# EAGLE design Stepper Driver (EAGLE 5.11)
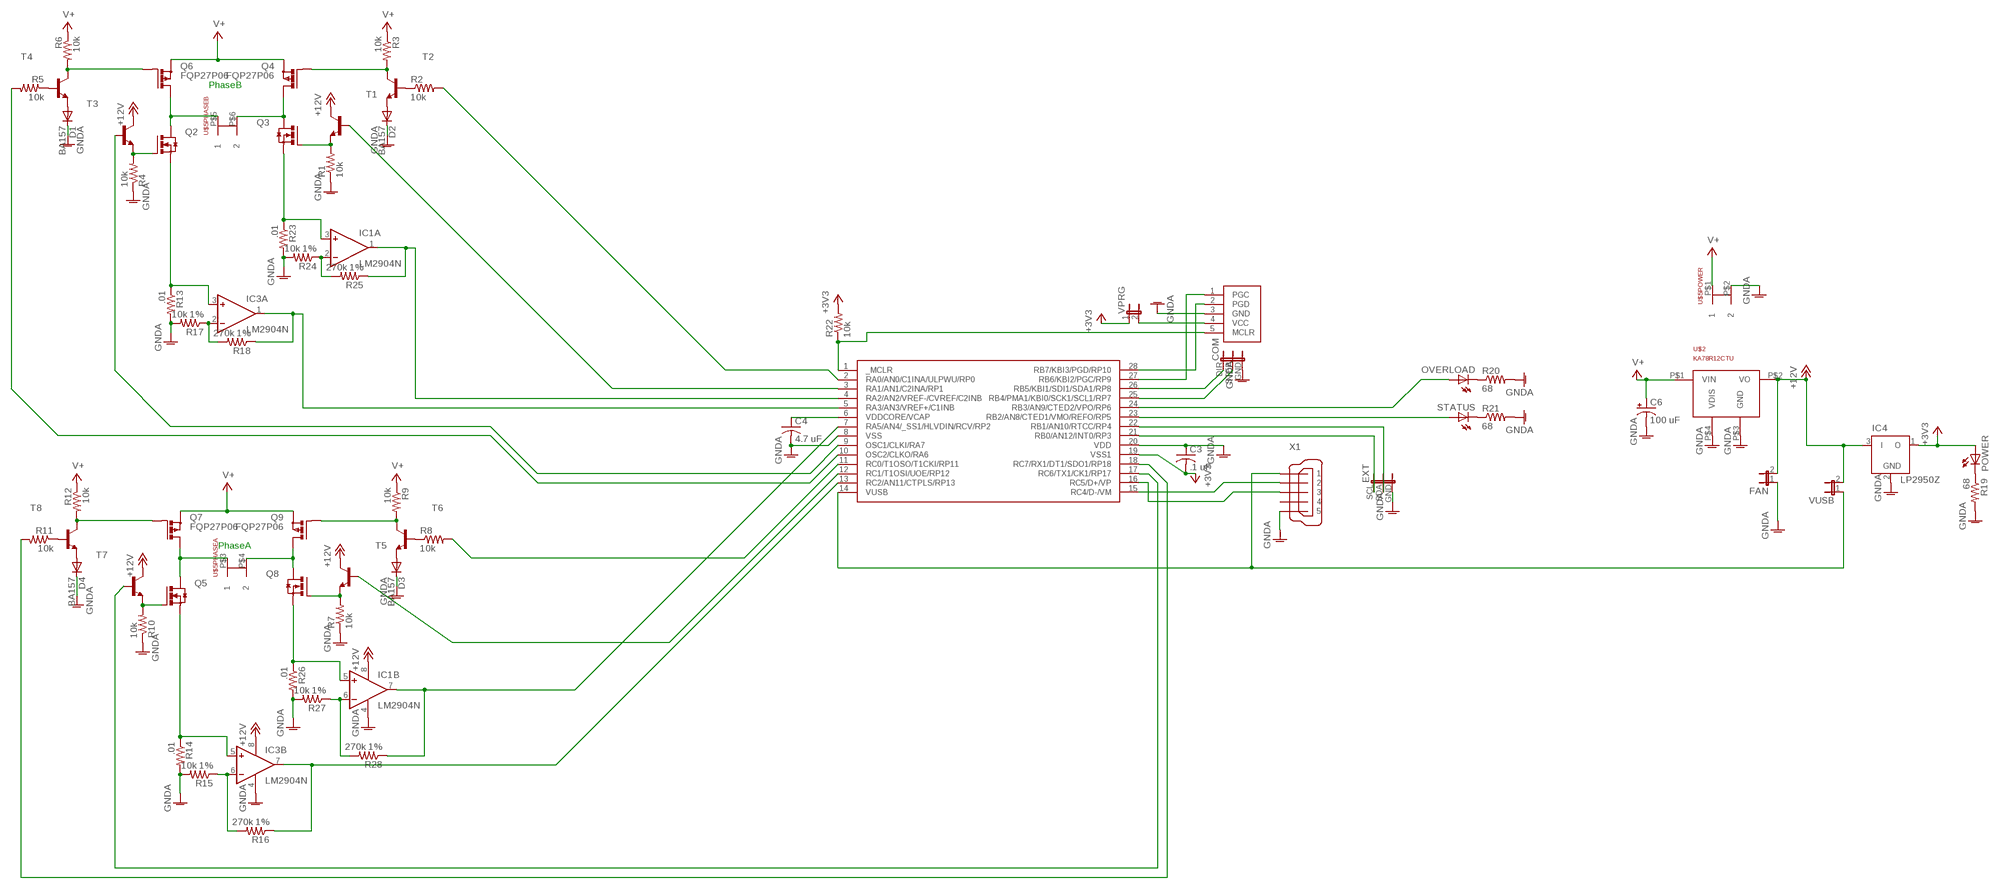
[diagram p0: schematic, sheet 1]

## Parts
C3  .1 uF  C-US025-024X044  [C025-024X044]
C4  4.7 uF  C-US025-024X044  [C025-024X044]
C6  100 uF  CPOL-USE5-10.5  [E5-10,5]
COM  COM  [COM]
D1  BA157  [P1-10]
D2  BA157  [P1-10]
D3  BA157  [P1-10]
D4  BA157  [P1-10]
EXT  I2C  [I2C]
FAN  JP1E  [JP1]
IC1  LM2904N  LM358N  [DIL08]
IC3  LM2904N  LM358N  [DIL08]
IC4  LP2950Z  [TO92]
OVERLOAD  LED3MM  [LED3MM]
POWER  LED3MM  [LED3MM]
Q2  IRF3704L-V  [TO262-V]
Q3  IRF3704L-V  [TO262-V]
Q4  FQP27P06  PMOSFET_PTO220BV  [TO220BV]
Q5  IRF3704L-V  [TO262-V]
Q6  FQP27P06  PMOSFET_PTO220BV  [TO220BV]
Q7  FQP27P06  PMOSFET_PTO220BV  [TO220BV]
Q8  IRF3704L-V  [TO262-V]
Q9  FQP27P06  PMOSFET_PTO220BV  [TO220BV]
R1  10k  R-US_0207/7  [0207/7]
R2  10k  R-US_0207/7  [0207/7]
R3  10k  R-US_0207/7  [0207/7]
R4  10k  R-US_0207/7  [0207/7]
R5  10k  R-US_0207/7  [0207/7]
R6  10k  R-US_0207/7  [0207/7]
R7  10k  R-US_0207/7  [0207/7]
R8  10k  R-US_0207/7  [0207/7]
R9  10k  R-US_0207/7  [0207/7]
R10  10k  R-US_0207/7  [0207/7]
R11  10k  R-US_0207/7  [0207/7]
R12  10k  R-US_0207/7  [0207/7]
R13  .01  R-US_0207/7  [0207/7]
R14  .01  R-US_0207/7  [0207/7]
R15  10k 1%  R-US_0207/7  [0207/7]
R16  270k 1%  R-US_0207/7  [0207/7]
R17  10k 1%  R-US_0207/7  [0207/7]
R18  270k 1%  R-US_0207/7  [0207/7]
R19  68  R-US_0207/7  [0207/7]
R20  68  R-US_0207/7  [0207/7]
R21  68  R-US_0207/7  [0207/7]
R22  10k  R-US_0207/7  [0207/7]
R23  .01  R-US_0207/7  [0207/7]
R24  10k 1%  R-US_0207/7  [0207/7]
R25  270k 1%  R-US_0207/7  [0207/7]
R26  .01  R-US_0207/7  [0207/7]
R27  10k 1%  R-US_0207/7  [0207/7]
R28  270k 1%  R-US_0207/7  [0207/7]
STATUS  LED3MM  [LED3MM]
T1  -NPN-TO92-EBC  [TO92-EBC]
T2  -NPN-TO92-EBC  [TO92-EBC]
T3  -NPN-TO92-EBC  [TO92-EBC]
T4  -NPN-TO92-EBC  [TO92-EBC]
T5  -NPN-TO92-EBC  [TO92-EBC]
T6  -NPN-TO92-EBC  [TO92-EBC]
T7  -NPN-TO92-EBC  [TO92-EBC]
T8  -NPN-TO92-EBC  [TO92-EBC]
U$1  ICSP_HEADER  [ICSP_HEADER]
U$2  KA78R12CTU  [TO220-4]
U$3  PIC18F24J50  [DIL28-3]
U$5  6P_TERMINAL_BLOCK_5.08MM  [6P_TERMINAL_BLOCK_5_08MM]
VPRG  JP1E  [JP1]
VUSB  JP1E  [JP1]
X1  MINI-USB-32005-301  [32005-301]

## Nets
21: EXT.SCL U$3.21(RB0/AN12/INT0/RP3)
+3V3: C3.2 IC4.1(O) POWER.A R22.2 U$3.19(VSS1) VPRG.1
+12V: FAN.2 IC1.8(P:V+) IC3.8(P:V+) IC4.3(I) T1.C T3.C T5.C T7.C U$2.P$2(VO) VUSB.2
GNDA: C3.1 C4.2 C6.- COM.GND D1.C D2.C D3.C D4.C EXT.GND FAN.1 IC1.4(P:V-) IC3.4(P:V-) IC4.2(GND) R1.1 R4.1 R7.1 R10.1 R13.2 R14.2 R15.2 R17.2 R19.2 R20.2 R21.2 R23.2 R24.2 R26.2 R27.2 U$1.3(GND) U$2.P$3(GND) U$2.P$4(VDIS) U$3.8(VSS) U$5.P$2 X1.5
N$1: U$1.1(PGC) U$3.27(RB6/KBI2/PGC/RP9)
N$2: C4.1 U$3.6(VDDCORE/VCAP)
N$3: EXT.SDA U$3.22(RB1/AN10/RTCC/RP4)
N$4: IC3.7(B:OUT) R16.1 U$3.13(RC2/AN11/CTPLS/RP13)
N$5: R22.1 U$1.5(MCLR) U$3.1(_MCLR)
N$7: U$1.2(PGD) U$3.28(RB7/KBI3/PGD/RP10)
N$8: IC3.1(A:OUT) R18.1 U$3.5(RA3/AN3/VREF+/C1INB)
N$9: R5.2 U$3.10(OSC2/CLKO/RA6)
N$10: T3.B U$3.9(OSC1/CLKI/RA7)
N$11: IC1.3(A:+IN) Q3.3(S) R23.1
N$12: Q2.2(D) Q6.D U$5.P$5
N$13: Q3.2(D) Q4.D U$5.P$6
N$14: Q5.2(D) Q7.D U$5.P$3
N$15: Q8.2(D) Q9.D U$5.P$4
N$16: Q3.1(G) R1.2 T1.E
N$17: R2.1 T2.B
N$18: Q4.G R3.2 T2.C
N$19: Q2.1(G) R4.2 T3.E
N$20: R5.1 T4.B
N$21: Q6.G R6.2 T4.C
N$22: Q8.1(G) R7.2 T5.E
N$23: R8.1 T6.B
N$24: Q9.G R9.2 T6.C
N$25: Q5.1(G) R10.2 T7.E
N$26: R11.1 T8.B
N$27: Q7.G R12.2 T8.C
N$28: POWER.K(C) R19.1
N$29: OVERLOAD.K(C) R20.1
N$30: R21.1 STATUS.K(C)
N$31: IC1.5(B:+IN) Q8.3(S) R26.1
N$32: IC1.2(A:-IN) R24.1 R25.2
N$33: IC1.1(A:OUT) R25.1 U$3.4(RA2/AN2/VREF-/CVREF/C2INB)
N$34: D4.A T8.E
N$35: IC1.6(B:-IN) R27.1 R28.2
N$36: IC3.3(A:+IN) Q2.3(S) R13.1
N$37: IC3.5(B:+IN) Q5.3(S) R14.1
N$38: IC3.6(B:-IN) R15.1 R16.2
N$39: U$1.4(VCC) VPRG.2
N$40: IC3.2(A:-IN) R17.1 R18.2
N$41: R2.2 U$3.2(RA0/AN0/C1INA/ULPWU/RP0)
N$42: IC1.7(B:OUT) R28.1 U$3.7(RA5/AN4/_SS1/HLVDIN/RCV/RP2)
N$43: D3.A T6.E
N$44: D1.A T4.E
N$45: D2.A T2.E
N$46: U$3.14(VUSB) VUSB.1 X1.1
N$47: U$3.15(RC4/D-/VM) X1.2
N$48: U$3.16(RC5/D+/VP) X1.3
N$50: OVERLOAD.A U$3.24(RB3/AN9/CTED2/VPO/RP6)
N$51: COM.DIR U$3.26(RB5/KBI1/SDI1/SDA1/RP8)
N$52: COM.STEP U$3.25(RB4/PMA1/KBI0/SCK1/SCL1/RP7)
N$55: T7.B U$3.17(RC6/TX1/CK1/RP17)
N$56: R11.2 U$3.18(RC7/RX1/DT1/SDO1/RP18)
N$58: STATUS.A U$3.23(RB2/AN8/CTED1/VMO/REFO/RP5)
N$60: T1.B U$3.3(RA1/AN1/C2INA/RP1)
N$62: T5.B U$3.12(RC1/T1OSI/UOE/RP12)
N$63: R8.2 U$3.11(RC0/T1OSO/T1CKI/RP11)
V+: C6.+ Q4.S Q6.S Q7.S Q9.S R3.1 R6.1 R9.1 R12.1 U$2.P$1(VIN) U$5.P$1
Unconnected: U$3.20(VDD) X1.4

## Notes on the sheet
- PhaseB
- PhaseA

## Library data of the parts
C3 C4 = rcl:C-US: CAPACITOR, American symbol
C6 = rcl:CPOL-US: POLARIZED CAPACITOR, American symbol
COM = jumper:COM: This is for stepper driver I/O
D1-D4 = diode:BA157: DIODE
EXT = jumper:I2C: This is an I2C communication header
FAN VPRG VUSB = jumper:JP1E: JUMPER
IC1 IC3 = linear:LM358: OP AMP also LM158; LM258; LM2904 Source: http://cache.national.com/ds/LM/LM158.pdf
IC4 = linear:LP2950: 100 mA, Low Power Low Dropout Voltage Regulator Source: http://www.onsemi.com/pub/Collateral/LP2950-D.PDF
OVERLOAD POWER STATUS = led:LED: LED
Q2 Q3 Q5 Q8 = transistor-power:IRF3704: SMPS MOSFET HEXFET® Power MOSFET Source: http://www.irf.com/product-info/datasheets/data/irf3704.pdf
Q4 Q6 Q7 Q9 = transistor-power:PMOSFET_P: Power MOSFET P-Channel
R1-R28 = resistor:R-US_: RESISTOR, American symbol
T1-T8 = transistor:*-NPN-: NPN Transistror BF959 corrected 2008.03.06
U$1 = custom:ICSP_HEADER
U$2 = custom:KA78R12CTU: 12V, 1A, LDO Regulator
U$3 = microchip:PIC18F24J50
U$5 = custom:6P_TERMINAL_BLOCK_5.08MM: This is 3 of MBES-152 linked together for power (12-24V and gnd), phase A and phase B of a stepper motor
X1 = con-cypressindustries:MINI-USB-: MINI USB-B Conector Source: www.cypressindustries.com; OC_FARNELL: unknown; OC_NEWARK: unknown

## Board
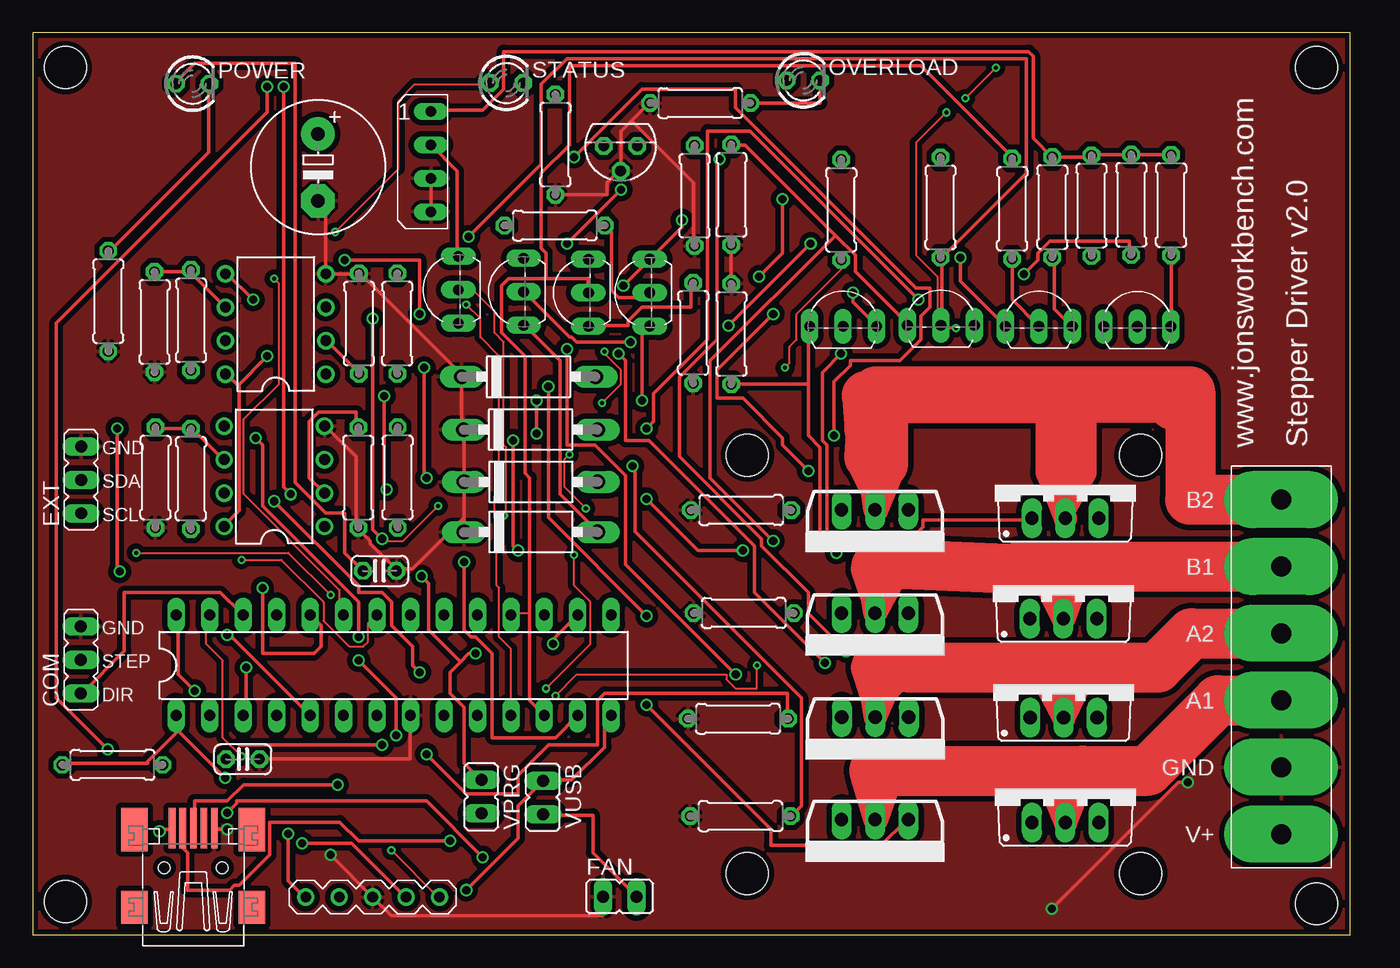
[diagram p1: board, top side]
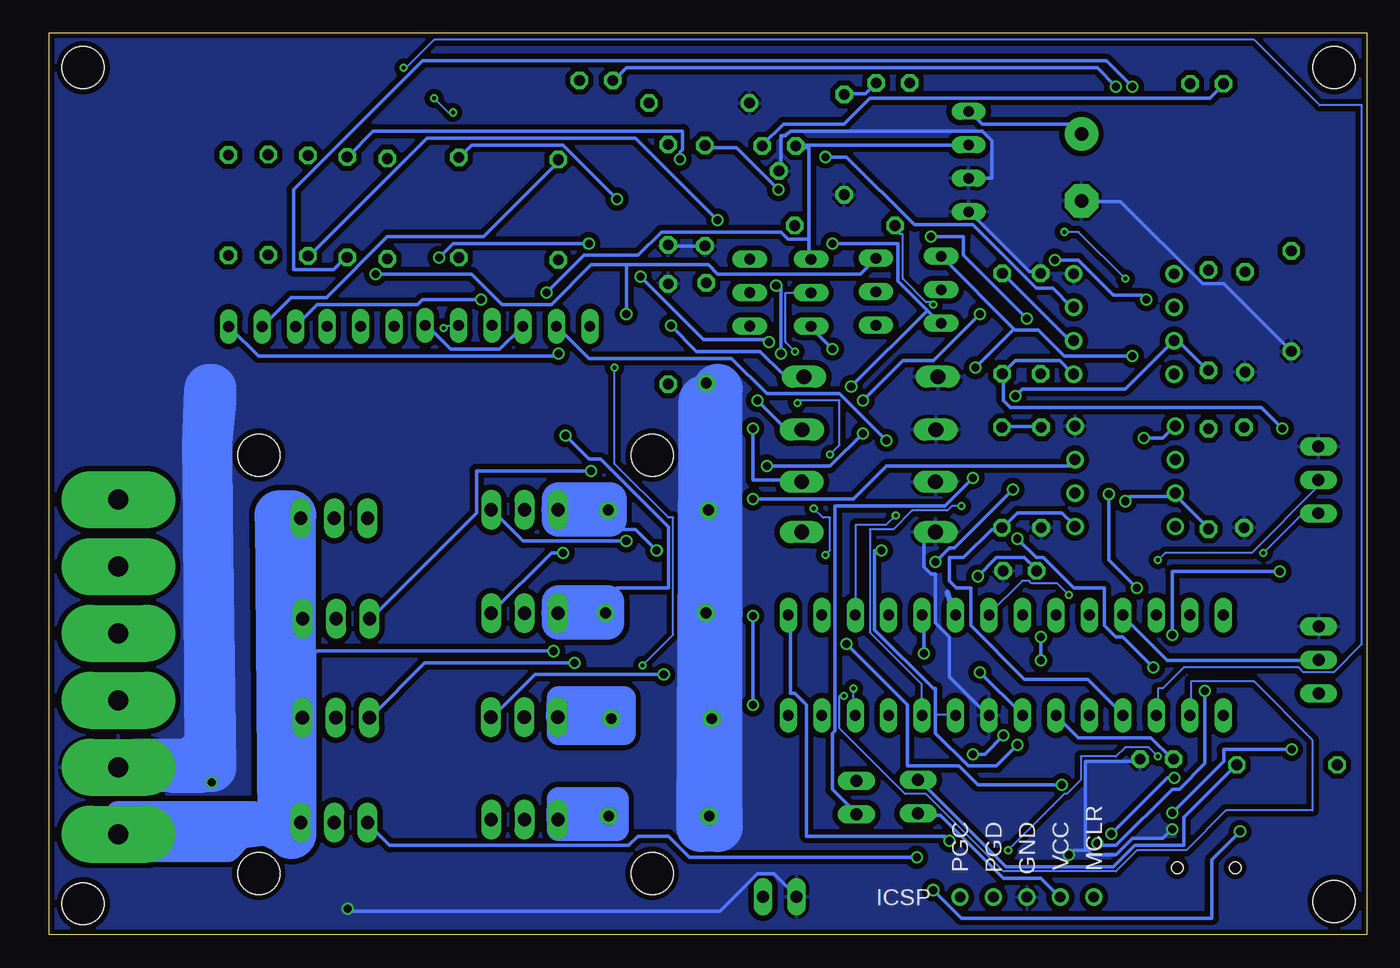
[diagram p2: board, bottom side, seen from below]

Size 100 x 68.44 mm. Coordinates in mm from the lower left corner, seen from the top.
Outline: 0,0 100,0 100,68.44 0,68.44 0,0
Copper layers (1*16): Top 0.035mm / dielectric 1.5mm / Bottom 0.035mm
Design rules "ITead_rule": minimum track width 6mil, minimum drill 12mil, track to track 6mil, track to pad 6mil, pad to pad 6mil, via to via 6mil, smd to smd 0mil, copper to edge 10mil, drill to drill 10mil, minimum pad ring 10mil, minimum via ring 6mil, stop-mask expansion 2mil, vias tented up to drill 100mil, thermal gap 10mil
Holes 3.2 mm at 84.07,4.65 84.07,36.4 54.23,4.65 54.23,36.4 97.41,2.34 2.46,2.51 2.46,65.81 97.41,65.81

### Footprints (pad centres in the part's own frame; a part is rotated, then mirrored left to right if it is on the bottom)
C025-024X044 = drill 0.813 octagon: 1 -1.27,0; 2 1.27,0
E5-10,5 = drill 1.016 pad 2.54 round: + -2.54,0 | drill 1.016 pad 2.54 octagon: - 2.54,0
COM = drill 0.9 pad 1.143 long: DIR -2.54,0; GND 2.54,0; STEP 0,0
P1-10 = drill 1.118 long: A 5.08,0; C -5.08,0
I2C = drill 0.9 pad 1.143 long: GND 2.54,0; SCL -2.54,0; SDA 0,0
JP1 = drill 0.914 long: 1 0,-1.27; 2 0,1.27
DIL08 = drill 0.813 pad 1.27 round: 1 -3.81,-3.81; 2 -1.27,-3.81; 3 1.27,-3.81; 4 3.81,-3.81; 5 3.81,3.81; 6 1.27,3.81; 7 -1.27,3.81; 8 -3.81,3.81
TO92 = drill 0.813 octagon: 1 -1.27,0; 2 0,1.905; 3 1.27,0
LED3MM = drill 0.813 octagon: A -1.27,0; K 1.27,0
TO262-V = drill 1.016 long: 1 -2.54,0; 2 0,0; 3 2.54,0
TO220BV = drill 1.016 long: D 0,-2.54; G -2.54,-2.54; S 2.54,-2.54
0207/7 = drill 0.813 octagon: 1 -3.81,0; 2 3.81,0
TO92-EBC = drill 0.813 long: B 0,-1.27; C 2.54,-1.27; E -2.54,-1.27
ICSP_HEADER = drill 0.8 round: 1 5.08,0; 2 2.54,0; 3 0,0; 4 -2.54,0; 5 -5.08,0
TO220-4 = drill 0.8 long: P$1 0,3.81; P$2 0,1.27; P$3 0,-1.27; P$4 0,-3.81
DIL28-3 = drill 0.813 long: 1 -16.51,-3.81; 2 -13.97,-3.81; 3 -11.43,-3.81; 4 -8.89,-3.81; 5 -6.35,-3.81; 6 -3.81,-3.81; 7 -1.27,-3.81; 8 1.27,-3.81; 9 3.81,-3.81; 10 6.35,-3.81; 11 8.89,-3.81; 12 11.43,-3.81; 13 13.97,-3.81; 14 16.51,-3.81; 15 16.51,3.81; 16 13.97,3.81; 17 11.43,3.81; 18 8.89,3.81; 19 6.35,3.81; 20 3.81,3.81; 21 1.27,3.81; 22 -1.27,3.81; 23 -3.81,3.81; 24 -6.35,3.81; 25 -8.89,3.81; 26 -11.43,3.81; 27 -13.97,3.81; 28 -16.51,3.81
6P_TERMINAL_BLOCK_5_08MM = drill 1.5 pad 4.318 long: P$1 -12.7,0; P$2 -7.62,0; P$3 -2.54,0; P$4 2.54,0; P$5 7.62,0; P$6 12.7,0
32005-301 = smd 3.1 x 0.5: 1 3,1.6; 2 3,0.8; 3 3,0; 4 3,-0.8; 5 3,-1.6 | smd 2.5 x 2: M1 -3,-4.45; M2 -3,4.45 | smd 3.3 x 2: M3 2.9,4.45; M4 2.9,-4.45 | hole 0.9: 0,2.2; 0,-2.2

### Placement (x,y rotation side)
C3  26.31,27.61 180 top
C4  15.93,13.31 0 top
C6  21.64,58.24 270 top
COM  3.63,20.85 90 top
D1  37.8,30.56 0 top
D2  37.8,34.37 0 top
D3  37.77,38.33 0 top
D4  37.62,42.34 0 top
EXT  3.66,34.52 90 top
FAN  44.53,2.87 270 top
IC1  18.32,34.79 90 top
IC3  18.42,46.35 90 top
IC4  44.6,59.87 180 top
OVERLOAD  58.47,64.85 0 top
POWER  12.12,64.59 0 top
Q2  63.91,24.41 180 top
Q3  63.91,32.26 180 top
Q4  78.36,34.14 0 top
Q5  63.91,8.74 180 top
Q6  78.21,26.52 0 top
Q7  78.36,11.05 0 top
Q8  63.93,16.51 180 top
Q9  78.23,19.01 0 top
R1  53.01,56.16 90 top
R2  61.34,55.02 270 top
R3  86.39,55.37 270 top
R4  53.01,45.59 270 top
R5  68.88,55.19 270 top
R6  83.36,55.4 270 top
R7  50.11,45.67 90 top
R8  39.6,53.82 180 top
R9  80.34,55.33 270 top
R10  50.22,56.08 90 top
R11  74.32,55.09 90 top
R12  77.37,55.22 270 top
R13  53.95,24.41 180 top
R14  53.7,8.99 180 top
R15  9.23,46.51 270 top
R16  12,46.63 90 top
R17  24.75,46.38 90 top
R18  27.64,46.38 90 top
R19  5.72,48.08 270 top
R20  50.65,63.12 180 top
R21  39.65,59.97 270 top
R22  6.04,12.88 0 top
R23  53.75,32.22 180 top
R24  24.69,34.7 270 top
R25  27.68,34.7 90 top
R26  53.52,16.38 180 top
R27  9.3,34.7 270 top
R28  11.99,34.59 90 top
STATUS  35.94,64.64 0 top
T1  68.91,47.52 0 top
T2  83.82,47.42 0 top
T3  61.49,47.45 0 top
T4  35.97,48.79 90 top
T5  40.89,48.72 90 top
T6  45.56,48.73 90 top
T7  31.01,48.95 90 top
T8  76.35,47.45 0 top
U$1  25.78,2.84 0 top
U$2  30.2,58.67 0 top
U$3  27.38,20.45 0 top
U$5  94.74,20.32 90 top
VPRG  34.04,10.46 180 top
VUSB  38.71,10.41 180 top
X1  12.17,5.08 90 top

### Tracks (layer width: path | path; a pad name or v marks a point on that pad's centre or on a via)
21  (via drill 0.3)
  Top 0.152: v22.58,25.78 19.38,28.98 v7.82,28.98
  Bottom 0.152: v22.58,25.78 23.47,26.67 25.43,26.67 25.6,26.85 26.14,26.85 28.63,24.36 U$3.21 | v7.82,28.98 4.98,31.83 3.73,31.83 EXT.SCL
+3V3  (via drill 0.61)
  Top 0.254: v33.6,21.34 33.07,21.34 32.45,20.71 | 32.45,20.71 31.65,19.91 31.65,18.31 32.72,17.25 32.72,12.98 33.96,11.73 VPRG.1 | v29.52,27.2 30.05,26.67 30.05,23.11 32.45,20.71 | POWER.A 10.85,64.72 12.27,66.14 19.91,66.14 19.91,34.31 22.23,32 23.65,32 23.65,28.98 24.89,27.74 C3.2
  Bottom 0.254: POWER.A 10.85,64.54 11.91,63.48 37.69,63.48 39.65,61.52 44.27,61.52 45.87,59.92 IC4.1 | R22.2 9.96,12.8 13.87,8.89 13.87,6.76 17.6,6.76 19.2,5.16 27.38,5.16 33.96,11.73 VPRG.1 | v33.6,21.34 33.6,24.18 U$3.19 | v29.52,27.2 28.09,28.63 25.96,28.63 25.07,27.74 C3.2
+12V  (via drill 0.61)
  Top 0.254: VUSB.2 38.76,9.07 42.49,9.07 42.49,6.22 45.7,3.02 FAN.2 | 15.56,41.69 14.76,42.49 IC3.8 | 15.56,41.69 15.65,41.6 15.65,32.18 14.58,31.11 IC1.8 | U$2.P$2 32.18,57.96 32.18,51.56 T7.C | v62.23,48.72 62.23,48.01 64.01,46.23 T3.C | 15.56,41.69 v17.78,43.92 | v29.87,34.67 29.69,34.85 v29.69,43.03
  Bottom 0.254: T3.C 64.19,46.05 65.79,44.45 69.52,44.45 71.3,46.23 T1.C | 42.32,52.81 42.32,59.74 43.2,59.74 IC4.3 43.2,59.92 30.23,59.92 U$2.P$2 | 42.32,52.81 42.32,51.38 T5.C | v62.23,48.72 59.38,51.56 55.3,51.56 53.52,53.34 44.45,53.34 43.92,52.81 42.32,52.81 | v17.78,43.92 22.94,43.92 24.89,45.87 26.67,45.87 26.76,45.96 | 26.76,45.96 T7.C | v29.87,34.67 32,32.54 40.36,32.54 40.36,15.47 40.54,15.29 40.54,11.02 38.76,9.25 VUSB.2 | 26.76,45.96 v29.69,43.03
GNDA  (via drill 0.61)
  Top 0.254: FAN.1 43.2,2.85 43.2,1.42 27.2,1.42 U$1.3 v22.58,6.04 | v87.66,11.56 86.94,11.56 v77.34,1.96 | R4.1 52.98,49.43 52.98,52.27 R1.1 | R21.2 39.65,56.19 43.56,56.19 43.56,57.07 44.45,57.96 IC4.2 44.63,57.96 44.63,60.98 45.43,61.78 | 45.43,61.78 46.76,63.12 R20.2 | R10.1 50.14,52.27 50.14,57.07 45.43,61.78 | C4.2 17.25,13.34 28.63,13.34 28.63,16.54 U$3.8 | v14.76,8 13.87,8 X1.5 | IC1.4 22.23,38.58 24.54,36.27 24.54,30.94 R24.2 24.71,30.76 25.6,29.87 25.6,29.69 27.56,27.74 C3.1 27.74,27.74 28.8,27.74 32.72,31.65 | D1.C 32.72,31.65 | 32.72,31.65 D2.C 32.72,38.23 D3.C 32.54,38.41 D4.C 32.54,42.49 24.89,50.14 R17.2 24.71,50.14 22.4,50.14 IC3.4 22.23,50.32 22.23,55.12 C6.- | U$2.P$4 30.23,54.94 30.23,57.25 U$2.P$3
  Bottom 0.254: R7.1 50.14,41.96 49.25,41.43 | v77.34,1.96 77.17,1.78 49.07,1.78 46.23,4.62 44.98,4.62 43.38,3.02 FAN.1 | v87.66,11.56 87.66,12.7 | R13.2 50.14,24.36 49.25,24.36 | R19.2 5.87,44.45 10.85,49.43 12.45,49.43 18.67,55.65 21.51,55.65 C6.- | R10.1 52.98,52.27 R1.1 | v14.76,8 15.47,7.29 17.78,7.29 19.02,6.04 20.8,6.04 21.25,6.49 | 21.25,6.49 21.34,6.58 21.34,13.16 17.25,13.16 C4.2 | U$2.P$4 30.05,54.76 25.6,50.32 24.89,50.32 R17.2 | U$3.8 28.8,16.71 31.65,19.56 31.65,22.58 32.72,23.65 32.72,27.38 33.07,27.38 33.6,27.91 33.6,30.4 32.72,30.4 D1.C | IC4.2 44.45,57.96 44.45,60.63 44.09,60.63 43.74,60.98 29.16,60.98 28.45,60.27 28.45,57.43 30.05,57.43 U$2.P$3 | v22.58,6.04 22.23,6.4 21.34,6.4 21.25,6.49
  Bottom 0.406: 31.29,24.18 31.83,25.96
  Bottom 1.778: R26.2 49.25,8.91 49.25,9.42 49.89,9.42 R14.2 49.61,16.64 49.61,16.36 49.96,16.36 49.96,24.89 49.94,24.89 R23.2
  Bottom 3.81: U$5.P$2 87.66,12.7 88.01,37.16 | 88.01,37.16 87.66,40.54 87.66,41.43 | 50.32,40.54 50.32,36.45 50.49,8.18 49.25,8.18 49.25,9.42 49.25,24.36 49.25,41.43 | 88.01,37.16 87.83,41.43 | 88.01,37.16 87.83,13.51 88.54,13.51 88.54,12.62 90.5,12.62 90.5,12.8 94.06,12.8 94.06,12.62 93.34,12.62 93.34,12.98 88.9,12.98 88.9,13.34
  pour Bottom (isolate 0.406): 0.36,68.1 99.57,68.1 99.57,0.36 0.36,0.36
  pour Top (isolate 0.406): 0.53,67.92 99.57,67.92 99.57,0.36 0.53,0.36
N$1  (via drill 0.3)
  Top 0.152: v27.2,6.4 30.76,2.85 U$1.1 | v15.82,13.51 14.4,14.94 14.4,20.8 13.16,22.05 13.16,24 U$3.27
  Bottom 0.152: v27.2,6.4 22.94,10.67 22.76,10.67 21.69,11.73 21.69,13.51 19.02,13.51 18.31,14.22 16.54,14.22 v15.82,13.51
N$2
  Bottom 0.254: C4.1 14.76,13.34 16.36,14.94 21.87,14.94 U$3.6
N$3  (via drill 0.3)
  Top 0.152: v15.82,28.45 18.85,28.45 22.05,25.25 22.05,23.82 24,21.87 25.07,21.87 25.43,22.23 25.43,23.65 25.96,24.18 U$3.22
  Bottom 0.152: v15.82,28.45 15.29,28.98 8.71,28.98 3.73,33.96 3.73,34.49 EXT.SDA
N$4  (via drill 0.61)
  Top 0.254: v32.72,28.27 32.72,23.11 33.25,22.58 33.6,22.58 34.85,21.34 34.85,14.94 39.65,14.94 U$3.13 | v26.85,33.78 26.67,33.96 v26.67,40.89
  Bottom 0.254: R16.1 12.09,42.85 14.22,44.98 14.58,44.98 IC3.7 14.76,44.98 18.31,41.43 26.14,41.43 v26.67,40.89 | v32.72,28.27 31.65,29.34 31.29,29.34 v26.85,33.78
N$5  (via drill 0.61)
  Top 0.254: v19.38,7.64 19.38,4.09 20.62,2.85 U$1.5 | 11.02,15.47 v14.58,11.91 | 11.02,15.47 11.02,16.54 U$3.1 11.02,15.47 | 11.02,15.47 8.71,13.16 8.71,12.98 2.31,12.98 R22.1
  Bottom 0.254: v19.38,7.64 15.11,11.91 v14.58,11.91
N$7  (via drill 0.61)
  Top 0.254: v20.45,6.93 24.18,6.93 28.27,2.85 U$1.2 | v12.27,18.49 11.02,19.74 11.02,24.18 U$3.28
  Bottom 0.254: v20.45,6.93 20.27,6.76 19.02,6.76 14.76,11.02 14.22,11.02 12.27,12.98 v12.27,18.49
N$8  (via drill 0.61)
  Top 0.254: v14.76,22.76 14.94,22.76 20.98,16.71 U$3.5 | v6.58,27.56 6.4,27.74 v6.4,38.41
  Bottom 0.254: v14.76,22.76 14.76,27.56 v6.58,27.56 | v6.4,38.41 8,40.01 27.03,40.01 27.56,40.54 27.56,42.49 R18.1 27.56,42.67 26.67,43.56 23.29,43.56 22.4,42.67 IC3.1
N$9  (via drill 0.3, 0.61)
  Top 0.152: v30.76,32.54 28.09,29.87 26.49,29.87 v26.49,30.05
  Top 0.254: 16,16.71 16.18,16.89 v16.18,20.27 | v26.49,30.05 25.78,30.76 v25.78,46.76 | v33.07,52.98 38.58,58.5 38.58,64.54 40.54,66.5 75.39,66.5 75.39,57.78 68.99,51.38 | 68.99,51.38 68.99,46.41 | 68.99,51.38 R5.2
  Bottom 0.152: v30.76,32.54 31.47,32.54 31.83,32.18 34.49,32.18 35.92,30.76 37.69,30.76 37.69,22.94 33.78,19.02 33.78,16.71 U$3.10
  Bottom 0.254: v16.18,20.27 18.49,22.58 19.02,22.58 19.91,23.47 19.91,26.31 22.23,26.31 24.54,28.63 25.07,28.63 v26.49,30.05 | v25.78,46.76 30.58,51.56 30.58,52.98 v33.07,52.98
N$10  (via drill 0.61)
  Top 0.254: 15.65,14.4 v26.49,14.4 | v36.8,29.16 36.45,29.52 v36.45,37.52 | T3.B 61.34,46.23
  Bottom 0.152: 32.72,16.71 31.29,16.71 U$3.9
  Bottom 0.254: v26.49,14.4 28.09,12.8 30.23,12.8 32.72,15.29 32.72,16.71 32.72,18.67 32.89,18.67 37.34,23.11 37.34,29.16 v36.8,29.16 | v36.45,37.52 40.01,41.07 45.52,41.07 48.18,43.74 59.03,43.74 61.34,46.05 T3.B
N$11  (via drill 0.61)
  Top 0.254: v46.58,33.07 50.49,29.16 v53.87,29.16
  Bottom 0.254: v46.58,33.07 38.94,33.07 36.45,35.56 22.58,35.56 22.23,35.92 IC1.3 | v53.87,29.16 55.47,30.76 56.36,30.76 57.43,31.47
  Bottom 2.54: 61.34,32.26 Q3.3 | 61.34,32.26 61.34,32.72 57.61,32.72 | 61.34,32.26 61.34,31.83 57.56,31.83 R23.1 57.61,32.22 57.61,31.47 61.34,31.47 61.34,33.07 57.43,33.07 57.43,31.47
N$12
  Top 1.778: Q2.2 63.3,28.09 62.94,27.74 63.65,25.78 64.01,24.54 65.96,28.12 | Q6.D 75.92,28.63 78.23,24 79.65,27.94
  Top 3.81: U$5.P$5 79.65,27.94 76.28,27.94 76.28,27.91 74.85,27.94 74.85,27.74 65.96,28.12 64.01,27.94 64.01,27.91
N$13
  Top 1.778: Q3.2 63.48,35.38 62.59,35.92 63.83,33.43 65.25,35.2 64.01,32.18 64.01,35.74 | Q4.D 76.99,35.03 79.83,35.03 78.23,32.18 76.99,35.2 76.99,39.12 79.83,35.2 79.83,38.76 78.77,38.58 78.23,35.92 78.41,40.72
  Top 3.81: U$5.P$6 87.83,33.02 87.83,40.18 | 87.83,40.18 87.83,41.25 64.01,41.25 64.01,35.74 64.54,35.74 64.54,40.89 | 64.54,40.89 64.19,40.89 | 64.19,40.89 63.3,40.89 63.48,38.41 63.65,38.41 63.48,36.27 64.19,36.27 64.19,40.89 | 64.54,40.89 66.5,40.89 66.5,41.07 65.96,41.07 65.96,40.72 78.41,40.72 86.59,40.72 86.59,40.18 87.83,40.18
N$14
  Top 1.778: Q5.2 62.94,11.91 63.83,9.42 65.25,11.73 65.08,11.73 | 65.08,11.73 64.54,11.73 64.54,12.62 68.99,12.62 68.99,12.98 67.56,12.98 67.56,11.73 63.83,12.45 | 65.08,11.73 64.01,8.71 | Q7.D 77.34,11.02 78.41,8.53 79.65,11.73 79.65,12.45
  Top 3.81: U$5.P$3 89.97,17.78 84.63,12.45 79.65,12.45 63.83,12.45
N$15
  Top 1.778: Q8.2 63.48,19.38 63.65,18.14 62.94,20.27 63.83,17.96 64.01,16.71 65.25,19.56 64.54,18.14 66.5,20.27 | Q9.D 75.92,20.8 78.23,16.54 80.37,20.98 78.23,20.27
  Top 3.81: U$5.P$4 87.94,22.86 85.34,20.27 78.23,20.27 66.5,20.27 64.01,20.27
N$16  (via drill 0.61)
  Top 0.254: 60.9,53.07 54.05,59.92 53.16,59.92 R1.2 | 60.9,53.07 62.41,51.56 62.41,50.32 66.32,46.41 T1.E | v56.19,29.87 51.38,34.67 51.38,43.56 60.9,53.07
  Bottom 0.254: v56.19,29.87 64.01,29.87 66.32,32.18 Q3.1
N$17
  Bottom 0.254: R2.1 61.34,58.67 67.03,52.98 74.32,52.98 78.94,48.36 81.61,48.36 T2.B
N$18  (via drill 0.61)
  Top 0.254: T2.C 86.41,46.23 86.41,51.56 R3.2 | v61.34,44.09 59.92,42.67 59.92,37.52 60.27,37.16 60.27,30.4 67.03,30.4 67.56,30.94 67.56,31.47 75.74,31.47 Q4.G
  Bottom 0.254: v61.34,44.09 61.52,43.92 84.1,43.92 86.23,46.05 T2.C
N$19  (via drill 0.61)
  Top 0.254: 58.85,41.78 58.85,46.05 T3.E | 58.85,41.78 R4.2 | v60.98,28.98 59.74,30.23 59.74,36.98 58.85,37.87 58.85,41.78
  Bottom 0.254: v60.98,28.98 61.87,28.98 Q2.1
N$20  (via drill 0.61)
  Top 0.254: v45.34,44.98 41.25,44.98 40.89,45.34 40.72,45.34 37.34,48.72 T4.B | v55.12,49.96 56.9,51.74 v56.9,55.83
  Bottom 0.254: v45.34,44.98 45.52,45.16 50.32,45.16 v55.12,49.96 | v56.9,55.83 60.98,59.92 67.92,59.92 68.81,59.03 R5.1
N$21  (via drill 0.61)
  Top 0.254: v75.21,50.14 76.28,51.21 76.28,51.74 77.17,52.63 83.21,52.63 83.21,51.74 R6.2 | v58.85,35.2 56.9,37.16 56.9,37.69 53.87,40.72 51.92,40.72 51.92,42.85 v56.19,47.12
  Bottom 0.254: 56.19,50.85 58.85,50.85 61.87,47.83 65.61,47.83 67.92,50.14 v75.21,50.14 | 56.19,50.85 49.96,50.85 49.25,50.14 38.41,50.14 37.34,51.21 T4.C | v58.85,35.2 67.56,35.2 67.56,32 75.56,24 Q6.G | 56.19,50.85 v56.19,47.12
N$22  (via drill 0.61)
  Top 0.254: T5.E 42.32,46.23 45.16,46.23 45.16,46.58 46.23,47.65 49.96,47.65 49.96,49.43 R7.2 | v53.34,19.74 44.98,28.09 44.98,34.85 42.67,37.16 40.54,37.16 v40.54,44.45
  Bottom 0.254: v53.34,19.74 63.12,19.74 66.32,16.54 Q8.1 | v40.54,44.45 42.14,46.05 T5.E
N$23
  Top 0.254: R8.1 43.56,53.7 43.92,53.34 43.92,48.9 44.45,48.36 46.76,48.36 46.76,48.72 T6.B
N$24  (via drill 0.61)
  Top 0.254: v49.25,54.23 49.25,53.7 46.94,51.38 T6.C 46.76,51.21 v44.81,49.25 | v60.1,20.62 54.76,25.96 54.76,29.52 46.76,37.52 44.98,37.52 44.98,43.56 v44.45,44.09
  Bottom 0.254: v49.25,54.23 55.47,60.45 71.3,60.45 80.19,51.56 R9.2 | v60.1,20.62 71.48,20.62 75.56,16.54 Q9.G | v44.45,44.09 44.45,49.25 v44.81,49.25
N$25  (via drill 0.61)
  Top 0.254: v40.54,52.45 v44.63,56.54 | v46.58,17.42 56.01,8 56.01,6.76 64.36,6.76 66.32,8.71 Q5.1 | v46.58,24.18 39.12,31.65 v39.12,41.6
  Bottom 0.254: 33.34,47.38 35.56,49.61 35.56,52.45 v40.54,52.45 | 33.34,47.38 32.36,46.41 T7.E | v44.63,56.54 47.83,59.74 50.14,59.74 R10.2 | v46.58,17.42 v46.58,24.18 | v39.12,41.6 33.34,47.38
N$26
  Top 0.254: T8.B 76.28,46.23 74.32,48.18 R11.1
N$27  (via drill 0.61)
  Top 0.254: T8.C 78.77,46.23 77.52,47.47 77.52,51.38 R12.2 | v34.14,5.87 29.87,10.13 15.47,10.13 15.47,9.96 v14.76,9.25 | v5.69,14.05 1.78,17.96 1.78,46.41 17.78,62.41 v17.78,64.36
  Bottom 0.254: v34.14,5.87 51.38,5.87 52.98,7.47 55.3,7.47 56.01,6.76 74.14,6.76 75.74,8.36 Q7.G | v14.76,9.25 10.85,13.16 10.85,14.05 v5.69,14.05 | v17.78,64.36 19.74,66.32 71.65,66.32 81.43,56.54 81.43,50.49 78.41,50.49 77.52,51.38 R12.2
N$28
  Top 0.254: R19.1 5.87,51.92 13.34,59.38 13.34,64.54 POWER.K
N$29
  Top 0.254: R20.1 59.74,63.12 OVERLOAD.K
N$30
  Bottom 0.254: STATUS.K 37.34,64.54 38.05,63.83 39.65,63.83 R21.1
N$31  (via drill 0.61)
  Top 0.254: v16.89,37.69 17.42,37.16 17.42,32.54 24.71,25.25 v24.71,22.58 | v24.71,20.8 27.56,17.96 v27.56,15.11 | v29.87,13.69 32.89,10.67 36.8,10.67 36.8,12.09 39.12,14.4 42.85,14.4 42.85,17.78 43.38,18.31 57.25,18.31 57.25,16.54 R26.1
  Bottom 0.254: v16.89,37.69 15.47,37.69 14.58,38.58 IC1.5 | v24.71,20.8 v24.71,22.58 | v27.56,15.11 28.98,13.69 v29.87,13.69
  Bottom 1.778: Q8.3 61.34,17.96 56.36,17.96 56.36,15.29 61.34,15.29 61.34,17.6 59.92,16.54 R26.1
N$32
  Top 0.254: IC1.2 22.05,33.6 20.98,34.67 20.98,38.94 21.69,39.65 24.54,39.65 24.54,38.58 R24.1
  Bottom 0.254: R25.2 27.56,38.58 24.71,38.58 R24.1
N$33
  Bottom 0.254: U$3.4 18.49,16.71 21.16,19.38 25.96,19.38 30.05,23.47 30.05,26.31 31.11,26.31 31.65,26.85 31.65,28.63 30.58,28.63 28.45,30.76 27.74,30.76 R25.1 27.56,30.94 26.49,32 23.11,32 22.23,31.11 IC1.1
N$34  (via drill 0.61)
  Top 0.254: v70.41,51.38 70.41,49.61 73.79,46.23 T8.E | v52.81,46.23 v59.03,52.45
  Bottom 0.254: v70.41,51.38 69.34,52.45 v59.03,52.45 | v52.81,46.23 50.85,44.27 46.05,44.27 44.27,42.49 42.85,42.49 D4.A
N$35
  Top 0.254: R27.1 9.42,38.41 R28.2 12.09,38.41 14.4,36.09 IC1.6
N$36  (via drill 0.61)
  Top 0.254: v41.07,59.03 46.23,64.19 53.34,64.19 53.34,62.76 67.03,49.07 68.1,49.07 68.1,47.65 67.39,46.94 67.39,45.16 65.79,43.56 62.05,43.56 62.05,43.2 60.81,41.96 v60.81,37.87
  Bottom 0.254: v41.07,59.03 39.47,59.03 34.31,53.87 29.87,53.87 25.07,49.07 23.82,49.07 22.4,47.65 IC3.3 | v60.81,37.87 59.03,36.09 58.14,36.09 52.98,30.94 52.98,26.31 56.9,26.31 57.61,25.25
  Bottom 2.54: 61.34,24.41 Q2.3 | 61.34,24.41 61.34,24.89 57.96,24.89 | 61.34,24.41 61.34,24 57.76,24 R13.1 57.78,24.41 57.78,23.65 61.34,23.65 61.34,25.25 57.61,25.25 57.61,23.65
N$37  (via drill 0.61)
  Top 0.254: v16.71,48.18 14.76,50.14 IC3.5 | v23.65,51.21 29.34,51.21 v29.34,47.12 | v38.23,40.54 v38.23,38.05 | v45.52,35.56 45.7,35.38 45.7,30.58 58.32,17.96 58.32,9.78 57.61,9.07 R14.1
  Bottom 0.254: v16.71,48.18 17.07,48.54 19.2,48.54 21.87,51.21 v23.65,51.21 | v29.34,47.12 32.89,43.56 35.2,43.56 v38.23,40.54 | v38.23,38.05 40.72,35.56 v45.52,35.56
  Bottom 1.778: Q5.3 61.34,10.31 56.9,10.31 56.9,8 61.34,8 61.34,9.78 R14.1
N$38
  Top 0.254: R15.1 9.25,50.32 11.91,50.32 R16.2 12.09,50.32 12.09,50.14 14.58,47.65 IC3.6
N$39
  Bottom 0.254: U$1.4 23.29,2.85 24.71,4.27 27.56,4.27 32.36,9.07 33.96,9.07 VPRG.2
N$40
  Top 0.254: R17.1 24.71,42.67 22.4,44.98 IC3.2
  Bottom 0.254: R18.2 27.56,50.14 22.58,45.16 22.4,45.16 IC3.2
N$41  (via drill 0.3)
  Top 0.152: v39.65,18.14 41.25,19.74 52.63,19.74 52.63,19.38 53.34,18.67 54.94,18.67 v54.94,20.45 | v57.07,43.03 57.43,43.38 57.43,44.63 57.96,45.16 57.96,47.12 61.34,50.49 R2.2
  Bottom 0.152: v39.65,18.14 40.01,18.14 40.01,15.65 35.03,10.67 33.43,10.67 27.56,4.8 19.02,4.8 17.42,6.4 13.69,6.4 10.67,9.42 4.09,9.42 4.09,14.76 8.53,19.2 13.34,19.2 13.34,16.71 U$3.2 | v54.94,20.45 52.63,22.76 52.63,31.65 52.98,31.65 57.07,35.74 v57.07,43.03
N$42  (via drill 0.61)
  Top 0.254: v29.34,19.91 28.8,20.45 28.8,21.87 27.2,23.47 27.2,25.25 26.49,25.96 24.71,25.96 24.71,26.49 v18.31,32.89
  Bottom 0.152: U$3.7 26.14,16.71
  Bottom 0.254: R28.1 12.09,30.94 14.58,33.43 IC1.7 14.58,33.25 17.96,33.25 v18.31,32.89 | 26.14,16.71 v29.34,19.91
N$43  (via drill 0.61)
  Top 0.254: v46.23,40.54 46.23,45.52 46.76,46.05 T6.E
  Bottom 0.254: v46.23,40.54 44.09,38.41 42.85,38.41 D3.A
N$44
  Top 0.254: T4.E 37.34,46.23 40.01,43.56 40.01,33.43 D1.A
N$45  (via drill 0.61)
  Top 0.254: v67.21,48.18 54.41,60.98 51.21,60.98 51.21,45.16 47.12,41.07 47.12,38.94 v46.58,38.41
  Bottom 0.254: v67.21,48.18 71.65,48.18 72.01,47.83 79.65,47.83 81.25,46.23 T2.E | v46.58,38.41 46.58,34.49 43.03,34.49 D2.A
N$46  (via drill 0.61)
  Top 0.254: U$3.14 43.74,16.54 43.38,16.18 43.38,14.22 40.89,11.73 38.76,11.73 VUSB.1 36.8,9.78 36.8,7.29 v32.89,3.38 | v9.6,7.82 9.6,8 10.49,8 X1.1
  Bottom 0.254: v9.6,7.82 11.73,5.69 11.73,1.25 30.76,1.25 v32.89,3.38
N$47  (via drill 0.61)
  Top 0.254: v31.65,7.11 24.71,7.11 23.29,8.53 17.96,8.53 17.96,6.04 15.65,3.73 15.29,3.73 14.94,3.38 11.73,3.38 11.73,6.22 11.38,6.58 11.38,8 X1.2
  Bottom 0.254: v31.65,7.11 32,7.47 42.49,7.47 42.49,17.42 43.38,18.31 43.74,18.31 43.74,24.18 U$3.15
N$48  (via drill 0.61)
  Top 0.254: v39.47,22.05 39.47,22.4 41.25,24.18 U$3.16 | v23.11,11.38 16,11.38 14.76,10.13 12.27,10.13 12.27,8.18 X1.3
  Bottom 0.254: v39.47,22.05 34.85,17.42 34.85,12.8 30.94,12.8 29.52,11.38 v23.11,11.38
N$50  (via drill 0.61)
  Top 0.254: v17.42,26.31 17.42,21.34 21.34,21.34 21.87,21.87 21.87,23.47 21.16,24.18 U$3.24 | v19.56,33.43 19.02,33.96 v19.02,64.36
  Bottom 0.254: v17.42,26.31 19.56,28.45 v19.56,33.43 | v19.02,64.36 20.45,65.79 56.19,65.79 57.07,64.9 OVERLOAD.A
N$51
  Top 0.254: U$3.26 15.82,24.36 14.22,25.96 6.93,25.96 6.93,21.51 3.73,18.31 COM.DIR
N$52
  Bottom 0.254: U$3.25 18.49,24.18 15.11,20.8 3.73,20.8 COM.STEP
N$55  (via drill 0.3)
  Top 0.152: v35.74,31.83 35.92,32 35.92,36.98 35.74,37.16 35.74,44.98 35.03,45.7 35.03,47.3 33.43,48.9 32.36,48.9 T7.B
  Bottom 0.152: v35.74,31.83 36.45,31.11 38.76,31.11 38.76,24.36 U$3.17
N$56
  Top 0.152: 37.69,24.36 36.27,24.36 U$3.18
  Top 0.254: 38.76,16.71 37.69,17.78 37.69,24.36 37.69,34.67 37.34,35.03 37.34,43.92 35.56,45.7 35.56,49.25 36.09,49.78 38.94,49.78 | 38.94,49.78 42.14,49.78 42.14,48.72 | 38.94,49.78 38.94,51.74 38.58,52.09 38.58,57.78 40.72,59.92 40.72,65.96 67.39,65.96 74.32,59.03 R11.2
N$58  (via drill 0.3)
  Top 0.152: v18.31,49.78 18.67,49.43 18.67,41.78 16,39.12 16,33.43 23.29,26.14 23.29,24.54 U$3.23 | v22.94,53.34 27.74,58.14 27.74,63.3 28.98,64.54 34.67,64.54 STATUS.A
  Bottom 0.152: v18.31,49.78 21.87,53.34 v22.94,53.34
N$60  (via drill 0.3)
  Top 0.152: v73.08,65.79 v70.76,63.48 | v69.34,62.41 67.03,60.1 67.03,51.56 68.63,49.96 68.63,46.23 68.81,46.05 v70.05,46.05
  Bottom 0.152: v73.08,65.79 72.9,65.79 70.76,67.92 8.53,67.92 3.56,62.94 0.36,62.94 0.36,22.05 2.49,19.91 4.8,19.91 5.16,20.27 13.87,20.27 15.47,18.67 15.82,18.67 15.82,16.71 U$3.3 | v70.76,63.48 69.7,62.41 v69.34,62.41 | v70.05,46.05 69.88,46.23 68.99,46.23 T1.B
N$62  (via drill 0.3)
  Top 0.152: v38.94,18.67 42.32,22.05 42.32,25.25 41.07,26.49 v41.07,28.8 | v41.96,32.36 40.36,33.96 40.36,36.09 v40.72,36.45 | v43.2,40.36 44.63,41.78 44.63,42.85 43.38,44.09 v43.38,44.27
  Bottom 0.152: v38.94,18.67 38.94,16.71 U$3.12 | v41.07,28.8 40.72,29.16 40.72,31.65 41.25,31.65 v41.96,32.36 | v40.72,36.45 40.01,37.16 40.01,40.54 43.03,40.54 v43.2,40.36 | v43.38,44.27 44.09,44.98 44.09,48.72 T5.B
N$63  (via drill 0.3)
  Top 0.152: v32.89,47.83 33.96,46.76 33.96,45.34 35.38,43.92 35.38,33.6 35.03,33.25 35.03,31.65 35.38,31.29 35.38,29.87 35.2,29.69 35.2,26.49 35.38,26.31 35.38,22.58 36.27,21.69 U$3.11
  Bottom 0.152: v32.89,47.83 33.07,48.01 33.43,48.01 35.2,49.78 35.2,53.16 35.38,53.16 35.92,53.7 R8.2
V+  (via drill 0.61)
  Top 0.254: R3.1 86.23,59.21 R6.1 80.37,59.21 R9.1 80.19,59.03 R12.1 77.34,59.03 75.92,60.45 75.92,66.67 75.56,67.03 35.74,67.03 35.74,64.19 34.14,62.59 30.23,62.59 U$2.P$1 | v61.7,21.51 58.85,24.36 58.85,25.96 55.3,29.52 55.3,30.05 49.07,36.27 49.07,42.32 51.92,45.16 51.92,58.67 v52.09,58.85
  Bottom 0.254: Q4.S 80.9,31.65 82.5,31.65 | 82.32,8.36 81.08,7.64 Q7.S | Q9.S 80.72,16.54 80.9,15.82 | U$2.P$1 30.05,62.41 29.16,61.52 22.4,61.52 21.69,60.81 C6.+ | v61.7,21.51 79.65,21.51 79.83,21.34 81.61,21.34 | v52.09,58.85 52.09,59.38 51.92,59.56 51.92,60.98 75.39,60.98 77.34,59.03 R12.1
  Bottom 1.778: Q9.S 80.59,12.83 | Q7.S 80.9,15.82 81.41,15.82 | 81.61,20.65 81.61,20.8 80.75,20.8 Q6.S | Q4.S 80.9,28.3 | U$5.P$1 94.74,9.22 94.77,9.25 84.45,9.25 84.1,8.89 92.1,8.89 94.59,6.4 86.41,6.4 85.52,7.29 | 85.52,7.29 84.99,8 | 86.23,7.29 85.52,7.29 | 86.23,7.29 90.5,7.29 91.21,8 | 82.32,8.36 82.86,8.36 82.86,7.29 83.57,7.64 86.23,7.29
  Bottom 3.81: 81.61,7.62 81.61,20.8 81.61,21.34 81.61,31.83 82.5,31.83 82.5,31.65 82.32,8.36 | 91.21,8 91.21,8.18

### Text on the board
tPlace: www.jonsworkbench.com | Stepper Driver v2.0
